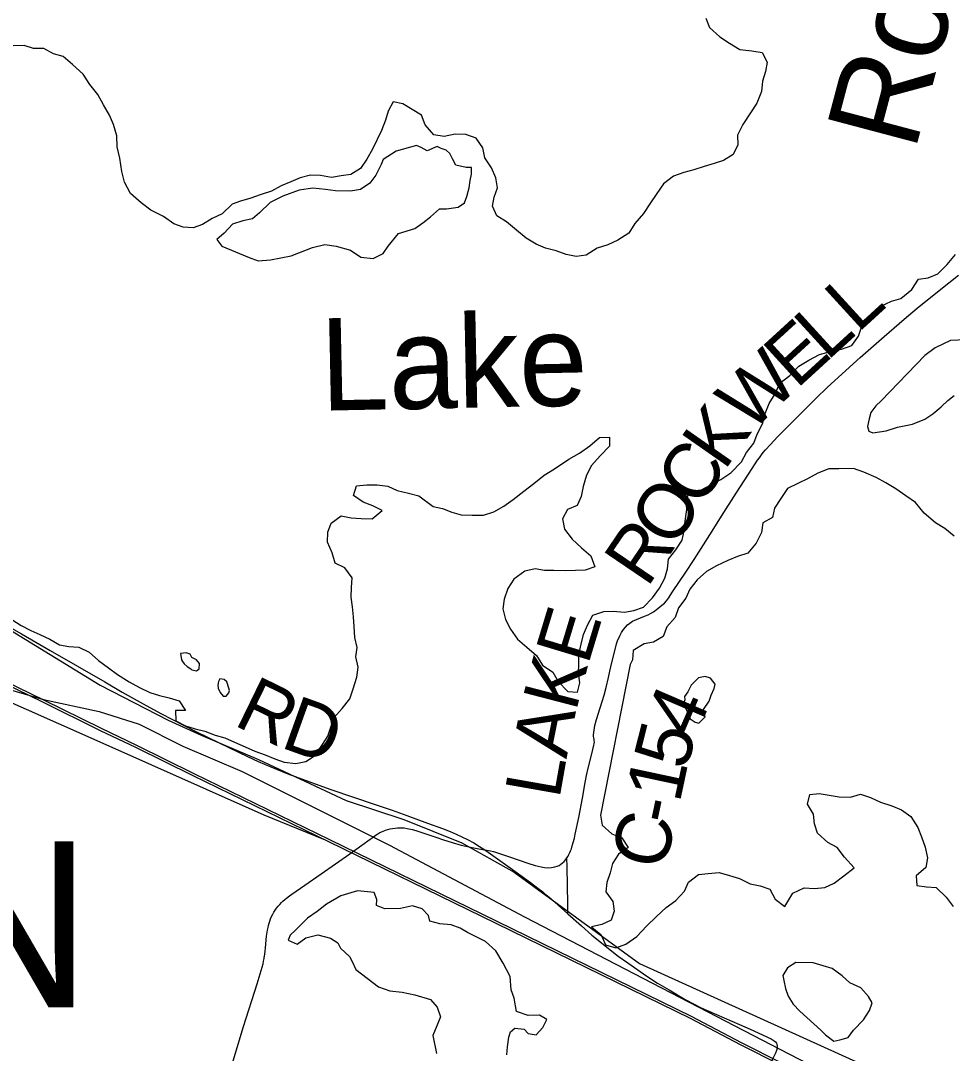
# Model space of a CAD drawing. Extents: x 0 to 34, y 0 to 22.
# Drawn here: x 3.606 to 4.562, y 15.128 to 16.187 of the extents above; entities that cross this region are included whole.
import ezdxf

# ---------------------------------------------------------------- set-up
doc = ezdxf.new("R2010")
doc.units = 0
for name, color, linetype in [('GM_X_County_Road', 7, 'Continuous'), ('GM_X_County_Road_Text', 7, 'Continuous'), ('GM_X_Major_Lake', 7, 'Continuous'), ('GM_X_Major_Lake_Text', 7, 'Continuous'), ('GM_X_Minor_Lake', 7, 'Continuous'), ('GM_X_Rail_Line', 7, 'Continuous'), ('GM_X_Township_Text', 7, 'Continuous')]:
    doc.layers.add(name, color=color, linetype=linetype)

msp = doc.modelspace()

# ---------------------------------------------------------------- linework, layer by layer
at = {"layer": 'GM_X_County_Road'}
for points in [[(4.1666, 15.3283), (4.1677, 15.3299), (4.1686, 15.3317), (4.1696, 15.3337), (4.1703, 15.3355), (4.1711, 15.3376), (4.172, 15.3405), (4.1731, 15.3441), (4.1742, 15.3485), (4.1751, 15.3525), (4.1788, 15.3695), (4.1825, 15.3896), (4.1853, 15.4055), (4.1867, 15.4129), (4.1884, 15.4203), (4.192, 15.4351), (4.1942, 15.4439), (4.1945, 15.4452), (4.1948, 15.447), (4.1946, 15.4482), (4.1945, 15.4497), (4.1942, 15.4513), (4.1939, 15.4528), (4.1939, 15.4544), (4.1941, 15.4568), (4.1944, 15.4593), (4.1953, 15.4642), (4.1969, 15.4703), (4.2008, 15.4822), (4.2028, 15.4887), (4.2048, 15.4952), (4.2069, 15.503), (4.2093, 15.5132), (4.2107, 15.5199), (4.2115, 15.5242), (4.2174, 15.548), (4.2186, 15.5511), (4.2209, 15.556), (4.2227, 15.5596), (4.2247, 15.5626), (4.2267, 15.565), (4.2289, 15.5672), (4.2312, 15.5692), (4.2339, 15.5711), (4.2421, 15.5746), (4.2461, 15.5761), (4.2499, 15.5776), (4.2523, 15.5789), (4.2553, 15.5807), (4.2599, 15.584), (4.2639, 15.5875), (4.2666, 15.5897), (4.2688, 15.5921), (4.2708, 15.5948), (4.2749, 15.6012), (4.2886, 15.6215), (4.2972, 15.6344), (4.3068, 15.6496), (4.3174, 15.6664), (4.3254, 15.6789), (4.3402, 15.7024), (4.3566, 15.7279), (4.3621, 15.7362), (4.3642, 15.7389), (4.3662, 15.7417), (4.3682, 15.7443), (4.3705, 15.7471), (4.3754, 15.7526), (4.3827, 15.7602), (4.4032, 15.7807), (4.422, 15.7996), (4.4342, 15.8112), (4.4676, 15.8417), (4.4922, 15.8634), (4.5129, 15.8812), (4.5263, 15.8923), (4.5504, 15.9118), (4.5685, 15.9261)], [(3.5573, 15.586), (3.6065, 15.558), (3.636, 15.541), (3.6921, 15.5087), (3.7097, 15.4983), (3.7314, 15.4862), (3.7495, 15.4764), (3.7855, 15.4579), (3.8094, 15.4461), (3.8387, 15.4322), (3.8494, 15.4272), (3.8625, 15.4215), (3.8799, 15.4146), (3.923, 15.3988), (3.9483, 15.3903), (3.9676, 15.3836), (3.987, 15.377), (4.0023, 15.3717), (4.0232, 15.3639), (4.0388, 15.3582), (4.0467, 15.3552), (4.0527, 15.3526), (4.0585, 15.3499), (4.0646, 15.3469), (4.0708, 15.3435), (4.0767, 15.34), (4.0823, 15.3363)], [(3.8558, 15.2262), (3.856, 15.2273), (3.8563, 15.2293), (3.8566, 15.2324), (3.857, 15.236), (3.8581, 15.2478), (3.8591, 15.254), (3.8597, 15.2569), (3.8601, 15.2589), (3.8608, 15.2612), (3.8614, 15.2632), (3.8623, 15.2655), (3.8633, 15.2679), (3.8646, 15.2704), (3.8656, 15.2724), (3.867, 15.2745), (3.8684, 15.2766), (3.87, 15.2786), (3.8716, 15.2805), (3.8733, 15.2823), (3.8747, 15.2837), (3.8767, 15.2854), (3.8785, 15.287), (3.8816, 15.2893), (3.884, 15.2911), (3.8974, 15.3002), (3.9143, 15.3117), (3.9437, 15.3325), (3.9559, 15.3411), (3.9644, 15.3473), (3.9674, 15.3495), (3.9695, 15.351), (3.9722, 15.3527), (3.9743, 15.3541), (3.977, 15.3554), (3.9801, 15.3567), (3.9825, 15.3574), (3.9849, 15.3581), (3.9874, 15.3585), (3.99, 15.3588), (3.9927, 15.3591), (3.9958, 15.3591), (3.9994, 15.3589), (4.0024, 15.3585), (4.0078, 15.3573), (4.0135, 15.3557), (4.0329, 15.3491), (4.0388, 15.3472)], [(4.0388, 15.3472), (4.0486, 15.3441), (4.0579, 15.3414), (4.0674, 15.3391), (4.076, 15.3373), (4.0823, 15.3363)], [(4.0823, 15.3363), (4.0881, 15.3322), (4.113, 15.3147), (4.1291, 15.303), (4.1367, 15.2971), (4.1417, 15.2932), (4.144, 15.2914), (4.1467, 15.2893), (4.1502, 15.2862), (4.1542, 15.2826), (4.1675, 15.2707)], [(4.0823, 15.3363), (4.0879, 15.3355), (4.0913, 15.3346), (4.0951, 15.3334), (4.1074, 15.3292), (4.1265, 15.3227), (4.134, 15.3204), (4.14, 15.3189), (4.1436, 15.3182), (4.1471, 15.318), (4.1507, 15.3182), (4.1542, 15.319), (4.1564, 15.3197), (4.1584, 15.3205), (4.1602, 15.3216), (4.162, 15.323), (4.1638, 15.3246), (4.1653, 15.3264), (4.1666, 15.3283)], [(4.1675, 15.2707), (4.1673, 15.2809), (4.1668, 15.3186), (4.1666, 15.3283)], [(4.1675, 15.2707), (4.1815, 15.2583), (4.1922, 15.2488), (4.219, 15.2274), (4.229, 15.2203), (4.2486, 15.2069), (4.2594, 15.1997), (4.2714, 15.1926), (4.288, 15.1828), (4.3045, 15.1744), (4.3437, 15.1571), (4.3546, 15.1524), (4.3764, 15.1424), (4.3795, 15.1405), (4.3807, 15.1394), (4.3816, 15.1381), (4.3822, 15.1366), (4.3825, 15.1349), (4.3824, 15.1328), (4.3818, 15.1306), (4.3807, 15.1278), (4.3766, 15.1194)], [(3.8229, 15.1163), (3.8343, 15.155), (3.8485, 15.1988), (3.8545, 15.2196), (3.8551, 15.2223), (3.8556, 15.225), (3.8558, 15.2262)]]:
    msp.add_lwpolyline(points, dxfattribs=at)
at = {"layer": 'GM_X_Major_Lake'}
for p, q in [((3.862, 15.9421), (3.8835, 15.946)), ((3.7767, 15.5247), (3.7805, 15.5221)), ((4.2316, 15.5267), (4.201, 15.3721)), ((3.8083, 15.5022), (3.8106, 15.498)), ((4.2942, 15.5056), (4.2908, 15.4987))]:
    msp.add_line(p, q, dxfattribs=at)
for points in [[(4.3093, 16.1901), (4.3131, 16.1803), (4.3234, 16.1709), (4.3333, 16.1642), (4.344, 16.1578), (4.3565, 16.1564), (4.3671, 16.1546), (4.3721, 16.1447), (4.3706, 16.1353), (4.3673, 16.1254), (4.3663, 16.1147), (4.3614, 16.1029), (4.3551, 16.0927), (4.3472, 16.0808), (4.3416, 16.0698), (4.3421, 16.0599), (4.3372, 16.0501), (4.3274, 16.0439), (4.3176, 16.0408), (4.3074, 16.0377), (4.2969, 16.0342), (4.2867, 16.0315)], [(3.8229, 15.999), (3.8124, 15.9891), (3.8022, 15.9845), (3.7924, 15.9783), (3.7826, 15.9748), (3.7724, 15.9755), (3.7629, 15.9789), (3.7522, 15.9864), (3.7393, 15.9931), (3.7294, 16.0006), (3.7184, 16.01), (3.7122, 16.0217), (3.7095, 16.0327), (3.7075, 16.0463), (3.7047, 16.058), (3.7043, 16.0694), (3.7008, 16.0808), (3.6969, 16.0906), (3.6908, 16.1012), (3.685, 16.1117), (3.6766, 16.1219), (3.6697, 16.1325), (3.6587, 16.1426), (3.6491, 16.1505), (3.6393, 16.1535), (3.6294, 16.1587), (3.6188, 16.159), (3.6093, 16.162), (3.598, 16.1615)], [(4.2867, 16.0315), (4.2761, 16.028), (4.2656, 16.0199), (4.2588, 16.01), (4.2517, 15.9993), (4.245, 15.9894), (4.2364, 15.9791), (4.23, 15.9692), (4.2187, 15.9623), (4.2085, 15.9573), (4.1976, 15.9538), (4.1863, 15.9469), (4.1761, 15.9453), (4.1658, 15.9475), (4.1556, 15.9512), (4.1446, 15.9541), (4.1351, 15.9582), (4.1248, 15.9642), (4.1149, 15.9725), (4.1046, 15.9811), (4.0947, 15.9871), (4.0901, 15.9969), (4.0919, 16.0064), (4.0953, 16.0159), (4.0937, 16.0262), (4.0891, 16.0364), (4.0822, 16.0466), (4.0802, 16.0568), (4.0733, 16.067), (4.0627, 16.0707), (4.0517, 16.071), (4.0404, 16.0686), (4.0298, 16.0704), (4.021, 16.0806), (4.0171, 16.0904), (4.0076, 16.0964), (3.9981, 16.102), (3.9882, 16.1042), (3.983, 16.0947), (3.9801, 16.0852), (3.976, 16.0746), (3.967, 16.0555), (3.9611, 16.0452), (3.9547, 16.0357), (3.9445, 16.0296), (3.9347, 16.0283), (3.9249, 16.0264), (3.9135, 16.0286), (3.9033, 16.0289), (3.8927, 16.0261), (3.8829, 16.0219), (3.8731, 16.018), (3.8633, 16.0126), (3.8516, 16.0087), (3.8418, 16.0053), (3.8312, 16.0021), (3.8229, 15.999)], [(3.8835, 15.946), (3.9054, 15.9546), (3.9179, 15.9577), (3.9296, 15.9559), (3.9444, 15.9518), (3.955, 15.9447), (3.9675, 15.9433), (3.9777, 15.9483), (3.983, 15.9559), (3.9935, 15.9689), (4.0105, 15.974), (4.0184, 15.9801), (4.0263, 15.9862), (4.0357, 15.9942), (4.0428, 15.9943), (4.0549, 15.9959), (4.0613, 16.0005), (4.0639, 16.007), (4.0661, 16.0157), (4.0672, 16.0233), (4.0687, 16.0298), (4.0686, 16.0366), (4.0629, 16.0369), (4.0523, 16.0391), (4.0489, 16.0455), (4.0462, 16.0512), (4.0427, 16.0546), (4.0374, 16.0564), (4.0333, 16.0583), (4.0231, 16.0537), (4.017, 16.0574), (4.0121, 16.0593), (3.9913, 16.0534), (3.9777, 16.045), (3.9759, 16.0397), (3.9703, 16.029), (3.9643, 16.0206), (3.9545, 16.0141), (3.9443, 16.0125), (3.9288, 16.0128), (3.9185, 16.0142), (3.9057, 16.0156), (3.8917, 16.0136), (3.8747, 16.0074), (3.8619, 16.0009), (3.851, 15.9902), (3.8438, 15.984), (3.8336, 15.9821), (3.8231, 15.9786), (3.8144, 15.9694), (3.8069, 15.9629), (3.8123, 15.9561), (3.8263, 15.9502), (3.8404, 15.9442), (3.8495, 15.9409), (3.862, 15.9421)], [(4.5095, 15.9024), (4.5208, 15.9116), (4.5275, 15.9222), (4.5373, 15.9234), (4.5475, 15.9277), (4.5569, 15.9372), (4.5655, 15.9475)], [(4.0578, 15.6804), (4.0692, 15.6798), (4.0809, 15.6799), (4.0915, 15.6834), (4.1016, 15.6891), (4.1114, 15.696), (4.1223, 15.7045), (4.1325, 15.7125), (4.143, 15.7209), (4.1539, 15.7274), (4.1686, 15.7374), (4.1795, 15.7436), (4.1901, 15.7512), (4.1999, 15.7597), (4.2101, 15.7601), (4.2101, 15.7506), (4.2008, 15.7407), (4.1918, 15.7308), (4.1865, 15.7209), (4.1832, 15.7095), (4.181, 15.6992), (4.1769, 15.6897), (4.1671, 15.6858), (4.1619, 15.6763), (4.1639, 15.6657), (4.1719, 15.6552), (4.1814, 15.6465), (4.191, 15.6382), (4.1952, 15.6269), (4.1854, 15.6234), (4.1752, 15.623), (4.1646, 15.6229), (4.1532, 15.6232), (4.1434, 15.6231), (4.1339, 15.6249), (4.1233, 15.6226), (4.1121, 15.6141), (4.1057, 15.6046), (4.102, 15.5936), (4.1006, 15.5837), (4.1033, 15.5727), (4.1087, 15.5629), (4.1159, 15.5527), (4.1255, 15.5444), (4.1354, 15.5358), (4.1415, 15.526), (4.1522, 15.5189), (4.1575, 15.5091), (4.1675, 15.4989), (4.1773, 15.4982), (4.1799, 15.5077), (4.1783, 15.5176), (4.1786, 15.527), (4.1789, 15.5369), (4.1811, 15.5475), (4.1837, 15.5574), (4.1877, 15.5669), (4.1933, 15.5772), (4.2043, 15.5811), (4.2141, 15.5815), (4.2255, 15.5805), (4.2353, 15.5821), (4.2451, 15.5856), (4.2545, 15.5951), (4.2616, 15.605), (4.2672, 15.6153), (4.2698, 15.6248), (4.2709, 15.6347), (4.2784, 15.6442), (4.2847, 15.6541), (4.2869, 15.664), (4.288, 15.6739), (4.2898, 15.6857), (4.2889, 15.6959), (4.2934, 15.7054), (4.3032, 15.7051), (4.3149, 15.7113), (4.3247, 15.7166), (4.3349, 15.7235), (4.3458, 15.7346), (4.351, 15.7441), (4.3585, 15.7537), (4.3618, 15.7632), (4.3678, 15.7742), (4.37, 15.7841), (4.3741, 15.7944), (4.3804, 15.8043), (4.3853, 15.8153), (4.3954, 15.8234), (4.4048, 15.8329), (4.415, 15.8391), (4.4259, 15.8448), (4.4372, 15.848), (4.4486, 15.8503), (4.4591, 15.8542), (4.4659, 15.8637), (4.4692, 15.874), (4.4782, 15.8835), (4.4883, 15.8942), (4.4997, 15.8996), (4.5095, 15.9024)], [(4.564, 15.6582), (4.5545, 15.6661), (4.545, 15.6721), (4.5332, 15.6819), (4.5244, 15.6928), (4.5145, 15.6999), (4.5042, 15.707), (4.4939, 15.713), (4.484, 15.7186), (4.4715, 15.7242), (4.4609, 15.7279), (4.4457, 15.7274), (4.4355, 15.7274), (4.4242, 15.7231), (4.4137, 15.7173), (4.4035, 15.7123), (4.3929, 15.7073), (4.3862, 15.697), (4.3798, 15.6871), (4.3776, 15.6776), (4.3678, 15.6719), (4.3664, 15.662), (4.3608, 15.6513), (4.3522, 15.641), (4.3416, 15.6375), (4.3318, 15.6333), (4.3201, 15.6279), (4.3099, 15.6221), (4.3002, 15.6137), (4.2927, 15.6041), (4.2886, 15.5946), (4.2811, 15.5847), (4.2778, 15.5748), (4.2691, 15.5653), (4.2654, 15.5554), (4.2556, 15.5496), (4.2458, 15.5477), (4.2345, 15.5411), (4.2338, 15.5316), (4.2316, 15.5267)], [(3.5965, 15.573), (3.606, 15.5666), (3.6159, 15.5617), (3.6254, 15.5576), (3.6357, 15.5528), (3.6455, 15.5468), (3.655, 15.545), (3.6652, 15.5443), (3.6759, 15.5394), (3.6854, 15.5308), (3.6957, 15.5233), (3.7052, 15.5165), (3.717, 15.5087), (3.7276, 15.5031), (3.7383, 15.4978), (3.7481, 15.4949), (3.758, 15.4923), (3.7682, 15.4893), (3.7747, 15.4795), (3.7645, 15.4795), (3.765, 15.4688), (3.7749, 15.4636), (3.7847, 15.4607), (3.7946, 15.4581), (3.8052, 15.454), (3.8151, 15.4514), (3.8253, 15.4469), (3.836, 15.4421), (3.8459, 15.4376), (3.8565, 15.4339), (3.8667, 15.4298), (3.8762, 15.4265), (3.888, 15.425), (3.8985, 15.427), (3.9083, 15.4335), (3.9147, 15.4435), (3.9211, 15.453), (3.924, 15.4625), (3.9273, 15.472), (3.9356, 15.4815), (3.9435, 15.4915), (3.9472, 15.5017), (3.9509, 15.5135), (3.9523, 15.5238), (3.9499, 15.5344), (3.951, 15.5442), (3.9486, 15.5545), (3.9482, 15.5658), (3.9473, 15.5757), (3.9465, 15.5859), (3.9449, 15.5958), (3.9452, 15.6056), (3.9459, 15.6155), (3.9386, 15.6257), (3.9287, 15.6305), (3.9253, 15.6411), (3.9206, 15.6521), (3.9209, 15.6623), (3.9243, 15.6718), (3.9348, 15.6791), (3.945, 15.6773), (3.9553, 15.6766), (3.9666, 15.6763), (3.9768, 15.6847), (3.9673, 15.6896), (3.9574, 15.6933), (3.9475, 15.7001), (3.9505, 15.7099), (3.961, 15.7112), (3.9716, 15.7112), (3.9826, 15.7098), (3.9921, 15.7053), (4.0039, 15.7024), (4.0145, 15.6998), (4.0293, 15.6889)], [(4.0293, 15.6889), (4.0388, 15.6867), (4.0483, 15.683), (4.0578, 15.6804)], [(3.7805, 15.5221), (3.7812, 15.5213), (3.7862, 15.5202), (3.7888, 15.5221), (3.7891, 15.5278), (3.7861, 15.5316), (3.7815, 15.5338), (3.7796, 15.5372), (3.7754, 15.5387), (3.7728, 15.5383), (3.7698, 15.5379), (3.7706, 15.5315), (3.7717, 15.5296), (3.7736, 15.5273), (3.7767, 15.5247)], [(3.8106, 15.498), (3.8136, 15.4942), (3.8166, 15.4943), (3.8193, 15.4977), (3.82, 15.5), (3.8192, 15.5023), (3.8173, 15.5087), (3.8146, 15.5113), (3.8101, 15.512), (3.8089, 15.5091), (3.8079, 15.5055), (3.8083, 15.5022)], [(4.2908, 15.4987), (4.2871, 15.4938), (4.2875, 15.4903), (4.2864, 15.4858), (4.2914, 15.4756), (4.293, 15.471), (4.2983, 15.4673), (4.3021, 15.4666), (4.3085, 15.4731), (4.3069, 15.4772), (4.3069, 15.4803), (4.3125, 15.489), (4.3147, 15.4951), (4.3177, 15.502), (4.3188, 15.5065), (4.3138, 15.5125), (4.3085, 15.5144), (4.3017, 15.5128), (4.2968, 15.5082), (4.2942, 15.5056)], [(4.201, 15.3721), (4.2026, 15.3619), (4.2125, 15.3529), (4.2228, 15.3488), (4.2293, 15.339), (4.2195, 15.3321), (4.2135, 15.3225), (4.2109, 15.313), (4.2076, 15.3028), (4.2065, 15.2933), (4.2138, 15.2835), (4.215, 15.2736), (4.2121, 15.2641), (4.2023, 15.2599), (4.1917, 15.2575), (4.2016, 15.2492), (4.2062, 15.239), (4.2168, 15.2357), (4.227, 15.2396), (4.2383, 15.2476), (4.2484, 15.258), (4.2586, 15.2679), (4.2684, 15.2771), (4.2785, 15.2844), (4.2872, 15.2939), (4.2912, 15.3034), (4.3018, 15.3111), (4.3116, 15.3123), (4.323, 15.3131), (4.3336, 15.3102), (4.3438, 15.3069), (4.3548, 15.3016), (4.3651, 15.2994), (4.3749, 15.2961), (4.3803, 15.2859), (4.3902, 15.2784), (4.3984, 15.2921), (4.4101, 15.2975), (4.4207, 15.2968), (4.4313, 15.2977), (4.4411, 15.3023), (4.4509, 15.3096), (4.4614, 15.318), (4.4515, 15.3289), (4.4439, 15.3387), (4.4344, 15.344), (4.4237, 15.3534), (4.4206, 15.3632), (4.4198, 15.3731), (4.4136, 15.3833), (4.4158, 15.3931), (4.4256, 15.3943), (4.4461, 15.3907), (4.4578, 15.3904), (4.468, 15.3935), (4.4783, 15.3902), (4.4885, 15.3854), (4.5003, 15.3817), (4.5102, 15.3776), (4.5197, 15.3708), (4.527, 15.3595), (4.5305, 15.3497), (4.5343, 15.3391), (4.5367, 15.3281), (4.5352, 15.3182), (4.5251, 15.3098), (4.5259, 15.2999), (4.5358, 15.2985), (4.5456, 15.2978), (4.5559, 15.288), (4.5632, 15.2782)]]:
    msp.add_lwpolyline(points, dxfattribs=at)
at = {"layer": 'GM_X_Minor_Lake'}
for p, q in [((4.5342, 15.8438), (4.4891, 15.7972)), ((3.9498, 15.2135), (3.973, 15.1959)), ((4.4058, 15.1708), (4.4272, 15.1513))]:
    msp.add_line(p, q, dxfattribs=at)
for points in [[(4.576, 15.86), (4.5605, 15.8592), (4.5447, 15.8518), (4.5342, 15.8438)], [(4.4891, 15.7972), (4.4838, 15.7922), (4.4786, 15.7853), (4.4768, 15.7789), (4.4753, 15.7709), (4.4765, 15.766), (4.4807, 15.7645), (4.4943, 15.7665), (4.506, 15.7704), (4.5215, 15.7732), (4.5339, 15.7786), (4.5422, 15.7839), (4.5508, 15.7912), (4.5576, 15.7977), (4.564, 15.8027)], [(4.1049, 15.126), (4.1056, 15.1344), (4.107, 15.1442), (4.1085, 15.1495), (4.113, 15.1534), (4.1225, 15.1523), (4.1267, 15.1478), (4.135, 15.1467), (4.1418, 15.154), (4.1459, 15.1623), (4.1383, 15.1668), (4.1269, 15.1664), (4.1148, 15.1705), (4.1124, 15.1841), (4.1093, 15.1928), (4.1084, 15.2064), (4.1011, 15.22), (4.0935, 15.2329), (4.0828, 15.2423), (4.0646, 15.2516), (4.0569, 15.2561), (4.0475, 15.2594), (4.0361, 15.2605), (4.0259, 15.2634), (4.0243, 15.2691), (4.0178, 15.2759), (4.0079, 15.2788), (3.9955, 15.2761), (3.9796, 15.276), (3.9709, 15.2793), (3.9712, 15.2854), (3.9685, 15.2926), (3.9514, 15.2943), (3.9344, 15.2893), (3.9197, 15.2808), (3.91, 15.2731), (3.9002, 15.2662), (3.8878, 15.254), (3.8825, 15.249), (3.8803, 15.2437), (3.8894, 15.2396), (3.8984, 15.2461), (3.9109, 15.2493), (3.9238, 15.2459), (3.9314, 15.2411), (3.9341, 15.2354), (3.9433, 15.2268), (3.9459, 15.2219), (3.9498, 15.2135)], [(4.4272, 15.1513), (4.4321, 15.1464), (4.4405, 15.14), (4.4469, 15.1416), (4.4552, 15.1439), (4.4609, 15.1512), (4.471, 15.1619), (4.4773, 15.1714), (4.4799, 15.1794), (4.4761, 15.1858), (4.4685, 15.1948), (4.4571, 15.2), (4.4491, 15.2072), (4.4388, 15.2147), (4.4297, 15.2173), (4.4194, 15.2206), (4.4016, 15.2209), (4.393, 15.2155), (4.3881, 15.2075), (4.3893, 15.2022), (4.3909, 15.1942), (4.3936, 15.1863), (4.399, 15.178), (4.4058, 15.1708)], [(3.973, 15.1959), (3.9848, 15.1918), (3.9973, 15.1904), (4.0102, 15.1875), (4.0265, 15.1827), (4.0334, 15.1751), (4.0368, 15.1649), (4.0328, 15.1558), (4.0287, 15.1459), (4.0326, 15.1273)]]:
    msp.add_lwpolyline(points, dxfattribs=at)
at = {"layer": 'GM_X_Rail_Line'}
for points in [[(2.114, 15.838), (2.2107, 15.8167), (2.4004, 15.7736), (3.4587, 15.5403), (3.5611, 15.5106), (3.6292, 15.4907)], [(3.9168, 15.3472), (3.8555, 15.3721), (3.6811, 15.4496), (3.5751, 15.4964), (3.5085, 15.5145), (3.3145, 15.5646), (3.1805, 15.5975), (2.8328, 15.6756), (2.2738, 15.7973), (2.1316, 15.826)], [(3.595, 15.5619), (3.6872, 15.5056), (3.757, 15.4696), (3.7911, 15.454), (3.8499, 15.429), (3.94, 15.3872), (3.999, 15.3675), (4.0585, 15.3435), (4.1125, 15.3134), (4.241, 15.2199), (4.5328, 15.0878)], [(4.4283, 15.0941), (4.3449, 15.1364), (4.2935, 15.1634), (4.0791, 15.268), (3.922, 15.3448), (3.7829, 15.4124), (3.7238, 15.4413), (3.6877, 15.4587), (3.6283, 15.488), (3.5345, 15.5334)], [(4.4292, 15.0962), (4.3459, 15.1385), (4.2945, 15.1655), (4.0802, 15.2701), (3.923, 15.3468), (3.7839, 15.4145), (3.7248, 15.4434), (3.6887, 15.4608), (3.6294, 15.4901), (3.5355, 15.5355)], [(3.6292, 15.4907), (3.6862, 15.4783), (3.7272, 15.4655), (3.7722, 15.443), (3.833, 15.4167), (3.9842, 15.3411), (4.1228, 15.2676), (4.442, 15.1026), (4.466, 15.0946)]]:
    msp.add_lwpolyline(points, dxfattribs=at)

# ---------------------------------------------------------------- texts
at = {"layer": 'GM_X_County_Road_Text'}
for s, rotation, p in [('L', 42.4325, (4.465, 15.8661)), ('L', 42.4323, (4.4336, 15.8374)), ('E', 42.4294, (4.4023, 15.8087)), ('W', 43.7009, (4.3549, 15.7635)), ('K', 55.0793, (4.3282, 15.7247)), ('C', 56.9267, (4.303, 15.686)), ('O', 56.9115, (4.2757, 15.6441)), ('R', 55.8304, (4.2489, 15.6045)), ('E', 73.1468, (4.1881, 15.5251)), ('K', 75.4363, (4.1757, 15.4773)), ('R', 334.0232, (3.823, 15.4651)), ('4', 66.6784, (4.2973, 15.4487)), ('D', 340.2446, (3.871, 15.4421)), ('A', 78.6922, (4.166, 15.4291)), ('5', 75.734, (4.2894, 15.4171)), ('L', 80.0156, (4.1587, 15.3876)), ('1', 77.9634, (4.2822, 15.3834)), ('-', 78.0158, (4.2774, 15.3606)), ('C', 76.8091, (4.2665, 15.3139))]:
    msp.add_text(s, height=0.0568, rotation=rotation, dxfattribs=at).set_placement(p)
at = {"layer": 'GM_X_Major_Lake_Text'}
for s, height, rotation, p in [('Rockwell', 0.09473, 75.1742, (4.5237, 16.052)), ('Lake', 0.09474, 1.1732, (3.9139, 15.7871))]:
    msp.add_text(s, height=height, rotation=rotation, dxfattribs=at).set_placement(p)
at = {"layer": 'GM_X_Township_Text'}
msp.add_text('FRANKLIN', height=0.17045, rotation=0, dxfattribs=at).set_placement((2.5512, 15.1748))

doc.saveas('drawing.dxf')
